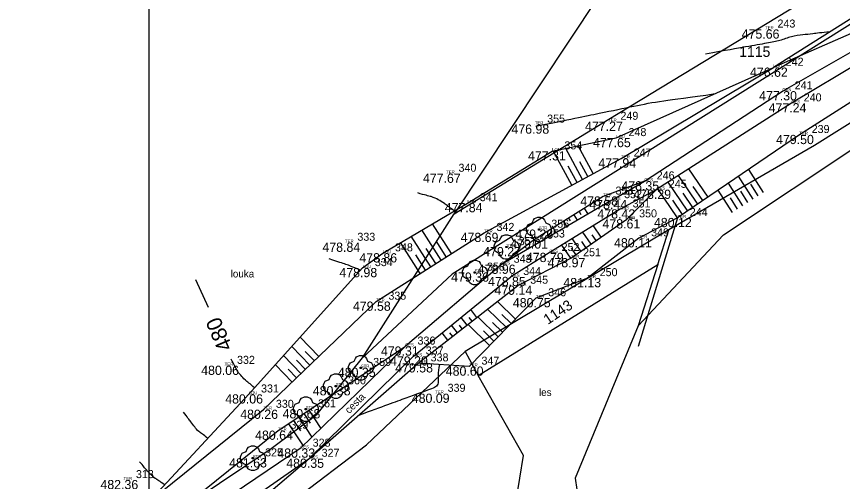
# Model space of a CAD drawing. Extents: x -604848 to -603227, y -1111879 to -1109838.
# Drawn here: x -603773.6 to -603639.4, y -1110601.8 to -1110526.3 of the extents above; entities that cross this region are included whole.
import ezdxf

# ---------------------------------------------------------------- set-up
doc = ezdxf.new("R2010")
doc.units = 0
for name, color, linetype in [('1', 7, 'Continuous'), ('10', 7, 'Continuous'), ('14', 7, 'Continuous'), ('18', 7, 'Continuous'), ('19', 7, 'Continuous'), ('20', 7, 'Continuous'), ('3', 7, 'Continuous'), ('4', 7, 'Continuous'), ('7', 7, 'Continuous'), ('8', 7, 'Continuous'), ('9', 7, 'Continuous'), ('Default', 7, 'Continuous')]:
    doc.layers.add(name, color=color, linetype=linetype)

# ---------------------------------------------------------------- blocks, each defined once
blk = doc.blocks.new('POINT_DISPLAY')
at = {"layer": 'Default'}
blk.add_line((0, 0), (0, 0), dxfattribs=at)
blk = doc.blocks.new('Z313')
at = {"layer": '3'}
for p, q in [((-1.1, 1.1), (-0.9, 1.5)), ((-0.9, 1.5), (-0.7, 1.8)), ((-0.7, 1.8), (-0.2, 2)), ((-0.2, 2), (0.2, 2)), ((0.2, 2), (0.7, 1.8)), ((0.7, 1.8), (0.9, 1.5)), ((0.9, 1.5), (1.1, 1.1)), ((-2, 0.2), (-1.9, 0.5)), ((-2, -0.2), (-2, 0.2)), ((-1.9, 0.5), (-1.7, 0.8)), ((-1.7, 0.8), (-1.1, 1.1)), ((-0.1, -0.1), (-0.1, 0.1)), ((-0.1, 0.1), (0.1, 0.1)), ((0.1, 0.1), (0.1, -0.1)), ((1.1, 1.1), (1.7, 0.8)), ((1.7, 0.8), (1.9, 0.5)), ((1.9, 0.5), (2, 0.2)), ((2, 0.2), (2, -0.2)), ((-1.8, -0.7), (-2, -0.2)), ((-1.5, -0.9), (-1.8, -0.7)), ((-1.1, -1.1), (-1.5, -0.9)), ((-0.8, -1.7), (-1.1, -1.1)), ((0.1, -0.1), (-0.1, -0.1)), ((1.1, -1.1), (0.8, -1.7)), ((1.5, -0.9), (1.1, -1.1)), ((1.8, -0.7), (1.5, -0.9)), ((2, -0.2), (1.8, -0.7)), ((-0.5, -1.9), (-0.8, -1.7)), ((-0.2, -2), (-0.5, -1.9)), ((0.2, -2), (-0.2, -2)), ((0.5, -1.9), (0.2, -2)), ((0.8, -1.7), (0.5, -1.9))]:
    blk.add_line(p, q, dxfattribs=at)

msp = doc.modelspace()

# ---------------------------------------------------------------- linework, layer by layer
at = {"layer": '1'}
for p, q in [((-603658.23, -1110491.66), (-603702.5, -1110558.36)), ((-603581.4, -1110507.54), (-603643.98, -1110547.3)), ((-603677.41, -1110543.01), (-603630, -1110514.23)), ((-603626.37, -1110520.17), (-603702.84, -1110568.16)), ((-603658.75, -1110561.77), (-603606.01, -1110526.72)), ((-603702.5, -1110558.36), (-603677.41, -1110543.01)), ((-603643.98, -1110547.3), (-603667.63, -1110560.99)), ((-603717.44, -1110581.77), (-603702.5, -1110558.36)), ((-603667.63, -1110560.99), (-603700.76, -1110580.75)), ((-603669.45, -1110566.59), (-603667.63, -1110560.99)), ((-603672.61, -1110576.59), (-603658.75, -1110561.77)), ((-603698.63, -1110584.62), (-603669.45, -1110566.59)), ((-603669.45, -1110566.59), (-603672.61, -1110576.59)), ((-603702.84, -1110568.16), (-603717.44, -1110581.77)), ((-603672.61, -1110576.59), (-603682.85, -1110601.29)), ((-603724.8, -1110590.91), (-603717.44, -1110581.77)), ((-603716.75, -1110595.9), (-603700.76, -1110580.75)), ((-603700.76, -1110580.75), (-603698.63, -1110584.62)), ((-603691.26, -1110597.62), (-603698.63, -1110584.62)), ((-603732.25, -1110596.47), (-603724.8, -1110590.91)), ((-603746.35, -1110605.91), (-603732.25, -1110596.47)), ((-603728.86, -1110605.05), (-603716.75, -1110595.9)), ((-603693.28, -1110610.14), (-603691.26, -1110597.62)), ((-603682.85, -1110601.29), (-603679.99, -1110621.11))]:
    msp.add_line(p, q, dxfattribs=at)
msp.add_lwpolyline([(-603752.05, -1110677.81), (-603752.05, -1109837.81), (-604346.05, -1109837.81), (-604346.05, -1110677.81), (-603752.05, -1110677.81)], dxfattribs=at)
at = {"layer": '10'}
for p, q in [((-603630.63, -1110521.95), (-603650.67, -1110534.62)), ((-603676.2, -1110546.05), (-603650.67, -1110534.62)), ((-603686.61, -1110548.2), (-603676.2, -1110546.05)), ((-603700.37, -1110556.62), (-603686.61, -1110548.2)), ((-603714.14, -1110564.77), (-603700.37, -1110556.62)), ((-603666.24, -1110559.04), (-603672.63, -1110579.9)), ((-603717.41, -1110567.17), (-603714.14, -1110564.77)), ((-603735.9, -1110587.69), (-603717.41, -1110567.17)), ((-603752.21, -1110605.22), (-603735.9, -1110587.69))]:
    msp.add_line(p, q, dxfattribs=at)
at = {"layer": '4'}
for p, q in [((-603649.21, -1110538.45), (-603627.08, -1110525.79)), ((-603625.96, -1110527.4), (-603647.74, -1110540.41)), ((-603671.63, -1110553.08), (-603649.21, -1110538.45)), ((-603647.74, -1110540.41), (-603669.65, -1110554.45)), ((-603676.91, -1110556.13), (-603671.63, -1110553.08)), ((-603669.65, -1110554.45), (-603675.54, -1110557.64)), ((-603676.91, -1110556.13), (-603694.86, -1110566.62)), ((-603675.54, -1110557.64), (-603687.07, -1110564.71)), ((-603687.07, -1110564.71), (-603693.31, -1110568.61)), ((-603694.86, -1110566.62), (-603710.48, -1110579.91)), ((-603709.15, -1110581.52), (-603693.31, -1110568.61)), ((-603710.48, -1110579.91), (-603727.52, -1110596.49)), ((-603709.15, -1110581.52), (-603726.06, -1110598.13)), ((-603727.52, -1110596.49), (-603748.22, -1110610.44)), ((-603746.64, -1110612.34), (-603726.06, -1110598.13))]:
    msp.add_line(p, q, dxfattribs=at)
at = {"layer": '7'}
for p, q in [((-603628.17, -1110524.78), (-603650.67, -1110534.62)), ((-603623.04, -1110530.67), (-603646.45, -1110545.55)), ((-603675.37, -1110549.37), (-603650.67, -1110534.62)), ((-603646.45, -1110545.55), (-603666.24, -1110559.04)), ((-603697.65, -1110561.45), (-603675.37, -1110549.37)), ((-603671.63, -1110553.08), (-603678.31, -1110555.55)), ((-603674.48, -1110559.25), (-603669.65, -1110554.45)), ((-603678.31, -1110555.55), (-603689.45, -1110562.52)), ((-603666.24, -1110559.04), (-603672.53, -1110562.33)), ((-603683.58, -1110565.56), (-603674.48, -1110559.25)), ((-603715.21, -1110572.62), (-603697.65, -1110561.45)), ((-603689.45, -1110562.52), (-603694.86, -1110566.62)), ((-603672.53, -1110562.33), (-603680.89, -1110568.8)), ((-603692.17, -1110570.03), (-603683.58, -1110565.56)), ((-603742.45, -1110573.57), (-603744.49, -1110569.08)), ((-603680.89, -1110568.8), (-603689.25, -1110572.06)), ((-603708.35, -1110582.64), (-603692.17, -1110570.03)), ((-603689.25, -1110572.06), (-603700.09, -1110583.17)), ((-603733.49, -1110590.18), (-603715.21, -1110572.62)), ((-603731.13, -1110593.58), (-603710.48, -1110579.91)), ((-603726.06, -1110598.13), (-603708.35, -1110582.64)), ((-603700.09, -1110583.17), (-603708.35, -1110582.64)), ((-603752.21, -1110605.22), (-603733.49, -1110590.18)), ((-603749.4, -1110608.24), (-603731.13, -1110593.58)), ((-603744.8, -1110614), (-603726.06, -1110598.13))]:
    msp.add_line(p, q, dxfattribs=at)
for points in [[(-603641.45, -1110528.79), (-603642.91, -1110528.97), (-603644.36, -1110529.14), (-603645.82, -1110529.31), (-603647.76, -1110529.53), (-603649.6, -1110530.29), (-603651.53, -1110530.63), (-603654.91, -1110531.22), (-603658.3, -1110531.82), (-603661.69, -1110532.42)], [(-603689.24, -1110544.14), (-603683.89, -1110543.05), (-603678.54, -1110541.95), (-603673.19, -1110540.86), (-603668.87, -1110539.98), (-603664.48, -1110539.52), (-603660.13, -1110538.85)], [(-603702.52, -1110557.89), (-603703.37, -1110557.3), (-603704.15, -1110556.6), (-603705.08, -1110556.1), (-603706.13, -1110555.54), (-603707.31, -1110555.35), (-603708.42, -1110554.98)], [(-603717.75, -1110567.54), (-603718.54, -1110567.23), (-603719.32, -1110566.88), (-603720.12, -1110566.59), (-603721.02, -1110566.27), (-603721.94, -1110566), (-603722.84, -1110565.7)], [(-603734.95, -1110586.64), (-603735.7, -1110585.95), (-603736.55, -1110585.37), (-603737.21, -1110584.58), (-603737.87, -1110583.8), (-603738.26, -1110582.86), (-603738.78, -1110581.99)], [(-603704.9, -1110582.86), (-603705.29, -1110584.15), (-603704.81, -1110586.27), (-603706.07, -1110586.73), (-603710.06, -1110588.2), (-603714.06, -1110589.66), (-603718.05, -1110591.12)], [(-603742.56, -1110594.84), (-603743.26, -1110594.23), (-603744.11, -1110593.75), (-603744.67, -1110593), (-603745.28, -1110592.2), (-603745.88, -1110591.4), (-603746.48, -1110590.59)], [(-603749.59, -1110602.4), (-603750.35, -1110601.82), (-603751.18, -1110601.34), (-603751.85, -1110600.67), (-603752.49, -1110600.04), (-603753.03, -1110599.33), (-603753.62, -1110598.66)]]:
    msp.add_open_spline(points, degree=3, dxfattribs=at)
at = {"layer": '8'}
for p, q in [((-603683.43, -1110553.74), (-603686.45, -1110548.17)), ((-603681.68, -1110552.79), (-603684.41, -1110547.75)), ((-603679.92, -1110551.83), (-603682.36, -1110547.33)), ((-603682.55, -1110553.26), (-603683.99, -1110550.61)), ((-603680.8, -1110552.31), (-603682.09, -1110549.92)), ((-603662.94, -1110556.79), (-603666.09, -1110552.17)), ((-603661.28, -1110555.66), (-603664.4, -1110551.09)), ((-603653.96, -1110555.99), (-603656.32, -1110552.28)), ((-603652.28, -1110554.91), (-603654.67, -1110551.16)), ((-603664.59, -1110557.92), (-603667.77, -1110553.25)), ((-603655.65, -1110557.06), (-603657.98, -1110553.41)), ((-603653.12, -1110555.45), (-603654.31, -1110553.58)), ((-603666.24, -1110559.04), (-603669.45, -1110554.33)), ((-603662.11, -1110556.23), (-603663.68, -1110553.93)), ((-603657.33, -1110558.14), (-603659.63, -1110554.54)), ((-603654.8, -1110556.53), (-603655.98, -1110554.69)), ((-603665.42, -1110558.48), (-603667.01, -1110556.13)), ((-603663.76, -1110557.35), (-603665.35, -1110555.03)), ((-603656.49, -1110557.6), (-603657.65, -1110555.79)), ((-603681.39, -1110557.47), (-603680.8, -1110558.41)), ((-603683.08, -1110558.54), (-603682.53, -1110559.42)), ((-603682.24, -1110558.01), (-603681.95, -1110558.46)), ((-603702.97, -1110564.83), (-603706.05, -1110559.98)), ((-603684.78, -1110559.6), (-603684.26, -1110560.43)), ((-603683.93, -1110559.07), (-603683.66, -1110559.49)), ((-603678.65, -1110562.14), (-603679.91, -1110560.32)), ((-603704.66, -1110565.91), (-603707.78, -1110561)), ((-603686.47, -1110560.66), (-603685.99, -1110561.44)), ((-603680.29, -1110563.28), (-603681.62, -1110561.37)), ((-603708.03, -1110568.05), (-603711.22, -1110563.04)), ((-603706.34, -1110566.98), (-603709.5, -1110562.02)), ((-603703.81, -1110565.37), (-603705.36, -1110562.93)), ((-603681.93, -1110564.42), (-603683.33, -1110562.41)), ((-603681.11, -1110563.85), (-603681.79, -1110562.87)), ((-603679.47, -1110562.71), (-603680.12, -1110561.77)), ((-603705.5, -1110566.45), (-603707.07, -1110563.98)), ((-603683.58, -1110565.56), (-603685.03, -1110563.46)), ((-603682.76, -1110564.99), (-603683.47, -1110563.96)), ((-603707.19, -1110567.52), (-603708.77, -1110565.02)), ((-603692.58, -1110575.47), (-603695.5, -1110572.62)), ((-603698.83, -1110575.22), (-603699.84, -1110573.93)), ((-603695.37, -1110578.33), (-603698.68, -1110575.1)), ((-603693.98, -1110576.9), (-603697.09, -1110573.86)), ((-603693.28, -1110576.19), (-603694.78, -1110574.71)), ((-603701.98, -1110577.68), (-603702.94, -1110576.46)), ((-603701.2, -1110577.06), (-603701.68, -1110576.44)), ((-603700.41, -1110576.45), (-603701.39, -1110575.19)), ((-603696.77, -1110579.76), (-603700.27, -1110576.34)), ((-603699.62, -1110575.83), (-603700.11, -1110575.2)), ((-603694.67, -1110577.62), (-603696.28, -1110576.05)), ((-603703.56, -1110578.91), (-603704.49, -1110577.72)), ((-603702.77, -1110578.29), (-603703.24, -1110577.69)), ((-603696.07, -1110579.05), (-603697.78, -1110577.39)), ((-603724.52, -1110581.56), (-603727.54, -1110578.42)), ((-603725.96, -1110582.95), (-603728.88, -1110579.91)), ((-603727.4, -1110584.34), (-603730.23, -1110581.4)), ((-603725.24, -1110582.26), (-603726.73, -1110580.71)), ((-603728.84, -1110585.72), (-603731.57, -1110582.89)), ((-603726.68, -1110583.64), (-603728.12, -1110582.15)), ((-603728.12, -1110585.03), (-603729.51, -1110583.58)), ((-603726.96, -1110590.82), (-603725.93, -1110592.38)), ((-603726.13, -1110590.27), (-603724.17, -1110593.23)), ((-603729.46, -1110592.48), (-603727.08, -1110596.07)), ((-603728.63, -1110591.92), (-603727.49, -1110593.64)), ((-603727.8, -1110591.37), (-603725.63, -1110594.65))]:
    msp.add_line(p, q, dxfattribs=at)

# ---------------------------------------------------------------- block references
at = {"layer": '18'}
for p in [(-603652, -1110528.42), (-603650.67, -1110534.62), (-603649.21, -1110538.45), (-603647.74, -1110540.41), (-603689.42, -1110543.86), (-603677.51, -1110543.4), (-603646.45, -1110545.55), (-603676.2, -1110546.05), (-603686.61, -1110548.2), (-603675.37, -1110549.37), (-603703.82, -1110551.84), (-603671.63, -1110553.08), (-603669.65, -1110554.45), (-603678.31, -1110555.55), (-603676.91, -1110556.13), (-603700.37, -1110556.62), (-603675.54, -1110557.64), (-603666.24, -1110559.04), (-603674.48, -1110559.25), (-603697.65, -1110561.45), (-603688.75, -1110560.93), (-603720.25, -1110563.05), (-603689.45, -1110562.52), (-603672.53, -1110562.33), (-603694.04, -1110563.76), (-603714.14, -1110564.77), (-603687.07, -1110564.71), (-603683.58, -1110565.56), (-603694.86, -1110566.62), (-603717.41, -1110567.17), (-603699.19, -1110567.9), (-603693.31, -1110568.61), (-603680.89, -1110568.8), (-603692.17, -1110570.03), (-603689.25, -1110572.06), (-603715.21, -1110572.62), (-603710.48, -1110579.91), (-603709.15, -1110581.52), (-603739.8, -1110583.04), (-603708.35, -1110582.64), (-603700.09, -1110583.17), (-603717.68, -1110583.38), (-603721.76, -1110586.36), (-603735.9, -1110587.69), (-603705.59, -1110587.58), (-603733.49, -1110590.18), (-603726.63, -1110590.1), (-603731.13, -1110593.58), (-603727.52, -1110596.49), (-603735.24, -1110598.07), (-603726.06, -1110598.13), (-603756.22, -1110601.6)]:
    msp.add_blockref('POINT_DISPLAY', p, dxfattribs=at)
at = {"layer": '3'}
for p in [(-603688.75, -1110560.93), (-603694.04, -1110563.76), (-603699.19, -1110567.9), (-603717.68, -1110583.38), (-603721.76, -1110586.36), (-603726.63, -1110590.1), (-603735.24, -1110598.07)]:
    msp.add_blockref('Z313', p, dxfattribs=at)

# ---------------------------------------------------------------- texts
at = {"layer": '14'}
msp.add_text('1115', height=1.7, dxfattribs=at).set_placement((-603656.22, -1110532.89))
msp.add_text('1143', height=1.7, rotation=33.7523, dxfattribs=at).set_placement((-603687.31, -1110576.44))
at = {"layer": '18'}
for s, p in [('TER', (-603652, -1110528.42)), ('LOU', (-603650.67, -1110534.62)), ('CES', (-603649.21, -1110538.45)), ('CES', (-603647.74, -1110540.41)), ('TER', (-603677.51, -1110543.4)), ('TER', (-603689.42, -1110543.86)), ('LOU', (-603676.2, -1110546.05)), ('TER', (-603646.45, -1110545.55)), ('LOU', (-603686.61, -1110548.2)), ('TER', (-603675.37, -1110549.37)), ('TER', (-603703.82, -1110551.84)), ('CES', (-603671.63, -1110553.08)), ('CES', (-603669.65, -1110554.45)), ('LOU', (-603700.37, -1110556.62)), ('TER', (-603678.31, -1110555.55)), ('CES', (-603676.91, -1110556.13)), ('CES', (-603675.54, -1110557.64)), ('TER', (-603674.48, -1110559.25)), ('TER', (-603666.24, -1110559.04)), ('TER', (-603697.65, -1110561.45)), ('STR', (-603688.75, -1110560.93)), ('TER', (-603720.25, -1110563.05)), ('TER', (-603689.45, -1110562.52)), ('TER', (-603672.53, -1110562.33)), ('LOU', (-603714.14, -1110564.77)), ('STR', (-603694.04, -1110563.76)), ('CES', (-603687.07, -1110564.71)), ('TER', (-603683.58, -1110565.56)), ('LOU', (-603717.41, -1110567.17)), ('CES', (-603694.86, -1110566.62)), ('STR', (-603699.19, -1110567.9)), ('CES', (-603693.31, -1110568.61)), ('TER', (-603680.89, -1110568.8)), ('TER', (-603692.17, -1110570.03)), ('TER', (-603715.21, -1110572.62)), ('TER', (-603689.25, -1110572.06)), ('CES', (-603710.48, -1110579.91)), ('CES', (-603709.15, -1110581.52)), ('TER', (-603739.8, -1110583.04)), ('STR', (-603717.68, -1110583.38)), ('TER', (-603708.35, -1110582.64)), ('TER', (-603700.09, -1110583.17)), ('STR', (-603721.76, -1110586.36)), ('LOU', (-603735.9, -1110587.69)), ('TER', (-603705.59, -1110587.58)), ('TER', (-603733.49, -1110590.18)), ('STR', (-603726.63, -1110590.1)), ('TER', (-603731.13, -1110593.58)), ('CES', (-603727.52, -1110596.49)), ('STR', (-603735.24, -1110598.07)), ('CES', (-603726.06, -1110598.13)), ('TER', (-603756.22, -1110601.6))]:
    msp.add_text(s, height=0.5, dxfattribs=at).set_placement(p)
at = {"layer": '19'}
for s, p in [('243', (-603650, -1110528.12)), ('242', (-603648.67, -1110534.32)), ('241', (-603647.21, -1110538.15)), ('240', (-603645.74, -1110540.11)), ('355', (-603687.42, -1110543.56)), ('249', (-603675.51, -1110543.1)), ('239', (-603644.45, -1110545.25)), ('248', (-603674.2, -1110545.75)), ('354', (-603684.61, -1110547.91)), ('247', (-603673.37, -1110549.07)), ('340', (-603701.82, -1110551.54)), ('246', (-603669.63, -1110552.78)), ('245', (-603667.65, -1110554.15)), ('341', (-603698.37, -1110556.32)), ('353', (-603676.31, -1110555.25)), ('352', (-603674.91, -1110555.83)), ('351', (-603673.54, -1110557.34)), ('350', (-603672.48, -1110558.95)), ('244', (-603664.24, -1110558.74)), ('342', (-603695.65, -1110561.15)), ('356', (-603686.75, -1110560.63)), ('333', (-603718.25, -1110562.75)), ('253', (-603687.45, -1110562.22)), ('349', (-603670.53, -1110562.03)), ('357', (-603692.04, -1110563.46)), ('348', (-603712.14, -1110564.47)), ('252', (-603685.07, -1110564.41)), ('251', (-603681.58, -1110565.26)), ('334', (-603715.41, -1110566.87)), ('343', (-603692.86, -1110566.32)), ('358', (-603697.19, -1110567.6)), ('344', (-603691.31, -1110568.31)), ('345', (-603690.17, -1110569.73)), ('250', (-603678.89, -1110568.5)), ('335', (-603713.21, -1110572.32)), ('346', (-603687.25, -1110571.76)), ('336', (-603708.48, -1110579.61)), ('337', (-603707.15, -1110581.22)), ('332', (-603737.8, -1110582.74)), ('359', (-603715.68, -1110583.08)), ('338', (-603706.35, -1110582.34)), ('347', (-603698.09, -1110582.87)), ('360', (-603719.76, -1110586.06)), ('331', (-603733.9, -1110587.39)), ('339', (-603703.59, -1110587.28)), ('330', (-603731.49, -1110589.88)), ('361', (-603724.63, -1110589.8)), ('329', (-603729.13, -1110593.28)), ('328', (-603725.52, -1110596.19)), ('325', (-603733.24, -1110597.77)), ('327', (-603724.06, -1110597.83)), ('318', (-603754.22, -1110601.3))]:
    msp.add_text(s, height=1.3, dxfattribs=at).set_placement(p)
at = {"layer": '20'}
for s, p in [('475.66 ', (-603655.82, -1110529.92)), ('476.62 ', (-603654.47, -1110536.12)), ('477.30 ', (-603652.98, -1110539.95)), ('477.24 ', (-603651.44, -1110541.91)), ('476.98 ', (-603693.22, -1110545.36)), ('477.27 ', (-603681.26, -1110544.9)), ('479.50 ', (-603650.23, -1110547.05)), ('477.65 ', (-603679.97, -1110547.55)), ('477.31 ', (-603690.53, -1110549.7)), ('477.94 ', (-603679.1, -1110550.87)), ('477.67 ', (-603707.6, -1110553.34)), ('478.35 ', (-603675.36, -1110554.58)), ('478.29 ', (-603673.43, -1110555.95)), ('478.58 ', (-603682.04, -1110557.05)), ('478.44 ', (-603680.57, -1110557.63)), ('477.84 ', (-603704.06, -1110558.12)), ('478.42 ', (-603679.25, -1110559.14)), ('480.12 ', (-603670.07, -1110560.54)), ('478.61 ', (-603678.43, -1110560.75)), ('478.69 ', (-603701.47, -1110562.95)), ('479.26 ', (-603692.57, -1110562.43)), ('478.84 ', (-603723.93, -1110564.55)), ('479.01 ', (-603693.42, -1110564.02)), ('480.11 ', (-603676.55, -1110563.83)), ('479.27 ', (-603697.81, -1110565.26)), ('478.86 ', (-603717.93, -1110566.27)), ('478.79 ', (-603690.87, -1110566.21)), ('478.97 ', (-603687.35, -1110567.06)), ('478.96 ', (-603698.68, -1110568.12)), ('478.98 ', (-603721.17, -1110568.67)), ('479.36 ', (-603703.01, -1110569.4)), ('478.85 ', (-603697.03, -1110570.11)), ('481.13 ', (-603684.79, -1110570.3)), ('479.14 ', (-603695.98, -1110571.53)), ('480.75 ', (-603692.99, -1110573.56)), ('479.58 ', (-603718.97, -1110574.12)), ('479.31 ', (-603714.42, -1110581.41)), ('479.20 ', (-603712.94, -1110583.02)), ('480.06 ', (-603743.62, -1110584.54)), ('479.58 ', (-603712.11, -1110584.14)), ('480.60 ', (-603703.89, -1110584.67)), ('480.35 ', (-603721.42, -1110584.88)), ('480.38 ', (-603725.49, -1110587.86)), ('480.06 ', (-603739.72, -1110589.19)), ('480.09 ', (-603709.41, -1110589.08)), ('480.26 ', (-603737.28, -1110591.68)), ('480.68 ', (-603730.4, -1110591.6)), ('480.64 ', (-603734.86, -1110595.08)), ('480.33 ', (-603731.25, -1110597.99)), ('481.63 ', (-603739.08, -1110599.57)), ('480.35 ', (-603729.8, -1110599.63)), ('482.36 ', (-603759.99, -1110603.1))]:
    msp.add_text(s, height=1.5, dxfattribs=at).set_placement(p)
at = {"layer": '7'}
msp.add_text('480', height=2.5, rotation=113.4, dxfattribs=at).set_placement((-603738.46, -1110580.04))
at = {"layer": '9'}
for s, p in [('louka', (-603738.84, -1110568.71)), ('les', (-603688.75, -1110587.96))]:
    msp.add_text(s, height=1.2, dxfattribs=at).set_placement(p)
msp.add_text('cesta', height=1.2, rotation=45, dxfattribs=at).set_placement((-603719.58, -1110590.92))

doc.saveas('drawing.dxf')
